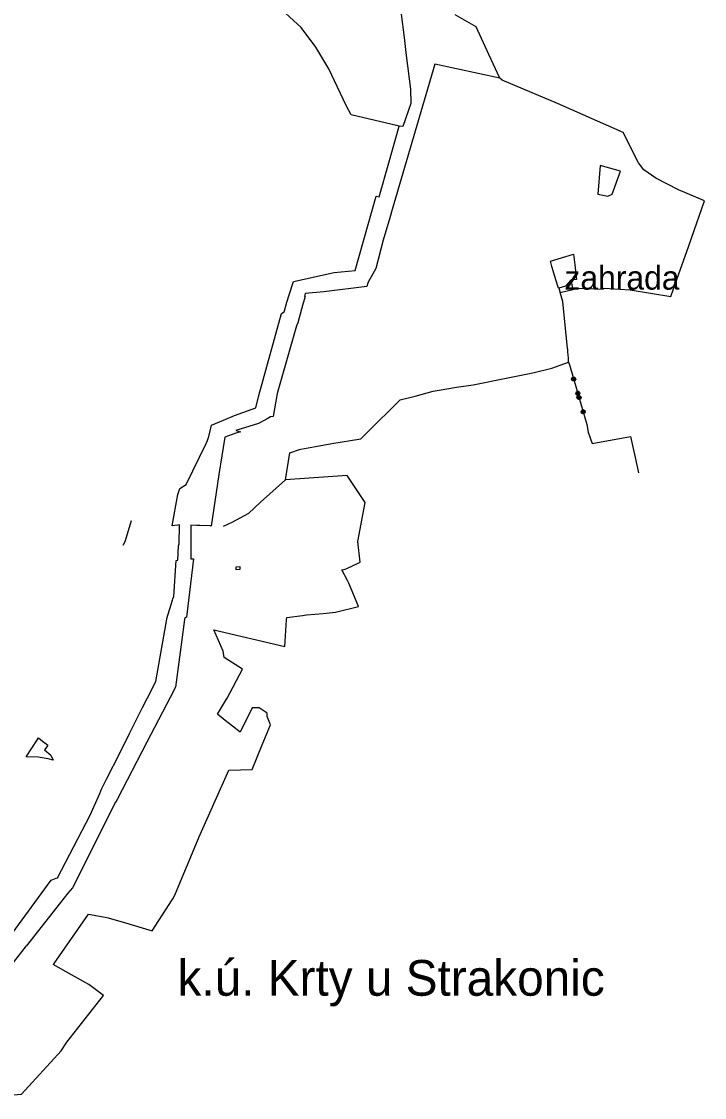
# Model space of a CAD drawing. Extents: x -800505 to -795586, y -1125317 to -1120396.
# Drawn here: x -796765 to -795617, y -1124292 to -1122485 of the extents above; entities that cross this region are included whole.
import ezdxf

# ---------------------------------------------------------------- set-up
doc = ezdxf.new("R2010")
doc.units = 0
for name, color, linetype in [('HRA_KU', 7, 'Continuous'), ('KU_OST', 7, 'Continuous'), ('LES_ZV', 7, 'Continuous'), ('Level 255', 7, 'Continuous'), ('OVNE_PRE', 7, 'Continuous'), ('OVNE_SET', 7, 'Continuous'), ('OVNI_SET', 7, 'Continuous'), ('TRV_POP', 7, 'Continuous'), ('TRV_ZV', 7, 'Continuous')]:
    doc.layers.add(name, color=color, linetype=linetype)

msp = doc.modelspace()

# ---------------------------------------------------------------- linework, layer by layer
at = {"layer": 'HRA_KU'}
for points in [[(-795845.8, -1123056.9), (-795843.6, -1123063.3), (-795814.8, -1123161.6), (-795812.6, -1123174.6), (-795806.1, -1123193.8), (-795741.5, -1123182.1), (-795734, -1123217), (-795728.4, -1123242.7)], [(-795833.7, -1123085.8), (-795835, -1123088.1), (-795837.6, -1123088.9), (-795839.9, -1123087.6), (-795840.7, -1123085), (-795839.4, -1123082.6), (-795836.8, -1123081.9), (-795834.5, -1123083.2), (-795833.7, -1123085.8), (-795834.1, -1123085.8), (-795834.8, -1123083.5), (-795835.8, -1123082.9), (-795834.7, -1123086.8), (-795835.2, -1123087.8), (-795836.8, -1123082.4), (-795837.5, -1123082.6), (-795836, -1123088), (-795836.7, -1123088.2), (-795838.3, -1123082.8), (-795839.1, -1123083.1), (-795837.5, -1123088.4), (-795838.5, -1123087.9), (-795839.6, -1123084), (-795840.2, -1123085), (-795839.5, -1123087.3)], [(-795826.7, -1123109.7), (-795828, -1123112.1), (-795830.6, -1123112.9), (-795832.9, -1123111.6), (-795833.7, -1123109), (-795832.4, -1123106.6), (-795829.8, -1123105.9), (-795827.4, -1123107.2), (-795826.7, -1123109.7), (-795827.1, -1123109.6), (-795827.8, -1123107.3), (-795828.8, -1123106.7), (-795827.7, -1123110.6), (-795828.2, -1123111.6), (-795829.8, -1123106.2), (-795830.6, -1123106.4), (-795829, -1123111.8), (-795829.8, -1123112), (-795831.3, -1123106.6), (-795832.1, -1123106.9), (-795830.5, -1123112.2), (-795831.5, -1123111.7), (-795832.6, -1123107.8), (-795833.2, -1123108.8), (-795832.5, -1123111.1)], [(-795824.6, -1123116.8), (-795825.9, -1123119.2), (-795828.5, -1123119.9), (-795830.8, -1123118.6), (-795831.6, -1123116), (-795830.3, -1123113.7), (-795827.7, -1123112.9), (-795825.4, -1123114.2), (-795824.6, -1123116.8), (-795825, -1123116.8), (-795825.7, -1123114.5), (-795826.7, -1123114), (-795825.6, -1123117.8), (-795826.1, -1123118.8), (-795827.7, -1123113.4), (-795828.4, -1123113.7), (-795826.9, -1123119), (-795827.6, -1123119.3), (-795829.2, -1123113.9), (-795830, -1123114.1), (-795828.4, -1123119.5), (-795829.4, -1123118.9), (-795830.5, -1123115.1), (-795831.1, -1123116.1), (-795830.4, -1123118.4)], [(-795817.6, -1123140.8), (-795818.9, -1123143.2), (-795821.5, -1123143.9), (-795823.8, -1123142.6), (-795824.6, -1123140), (-795823.3, -1123137.7), (-795820.7, -1123136.9), (-795818.3, -1123138.2), (-795817.6, -1123140.8), (-795818.1, -1123140.6), (-795818.7, -1123138.3), (-795819.7, -1123137.8), (-795818.6, -1123141.6), (-795819.1, -1123142.6), (-795820.7, -1123137.2), (-795821.5, -1123137.5), (-795819.9, -1123142.8), (-795820.7, -1123143.1), (-795822.3, -1123137.7), (-795823, -1123137.9), (-795821.4, -1123143.3), (-795822.4, -1123142.7), (-795823.6, -1123138.9), (-795824.1, -1123139.9), (-795823.4, -1123142.2)], [(-796321.4, -1123254.9), (-796363.2, -1123292.4), (-796383.6, -1123311), (-796411.3, -1123326.4), (-796426.1, -1123333.3)], [(-796580.8, -1123323.7), (-796591.5, -1123358.9), (-796594.9, -1123364.7)]]:
    msp.add_lwpolyline(points, dxfattribs=at)
at = {"layer": 'LES_ZV'}
for points in [[(-795961.3, -1122580.1), (-796070.3, -1122556.7), (-796142.1, -1122800.6), (-796146.2, -1122814.4), (-796157.1, -1122852.1), (-796169.6, -1122899.7), (-796182.7, -1122922.8), (-796183.2, -1122924.4), (-796184.6, -1122929.9), (-796256.9, -1122939), (-796288.3, -1122941.8), (-796289.7, -1122946.6), (-796288.5, -1122946.6), (-796292.7, -1122961.8), (-796294.3, -1122967.8), (-796300.7, -1122991.2), (-796303.1, -1122995.9), (-796335.5, -1123109.6), (-796342.3, -1123148.4), (-796346.6, -1123148.8), (-796352.3, -1123152), (-796366.7, -1123159.9), (-796405.1, -1123171.9), (-796397.1, -1123173.8), (-796404.8, -1123176.5), (-796423.6, -1123182.9), (-796433.7, -1123245.8)], [(-796511.9, -1123331.8), (-796502.4, -1123279.1), (-796498.9, -1123269.2), (-796488.5, -1123262.3), (-796454.9, -1123193.5), (-796452.7, -1123188.7), (-796450.3, -1123181.9), (-796446, -1123162.9), (-796425.4, -1123154.2), (-796407.1, -1123146.6), (-796371.3, -1123133.9), (-796366.4, -1123113.2), (-796328.3, -1122975.3), (-796323.6, -1122972.4), (-796323.2, -1122970.8), (-796318.9, -1122956.4), (-796314.7, -1122942), (-796307.8, -1122921.5), (-796239.5, -1122906.4), (-796204.2, -1122903.1), (-796169.1, -1122778.1), (-796163.8, -1122779.3), (-796147.7, -1122722), (-796130.5, -1122660.8)], [(-795792.8, -1122726.5), (-795796.3, -1122774.8), (-795779.7, -1122778.2), (-795772.5, -1122774.7), (-795758.6, -1122736.2), (-795792.8, -1122726.5)], [(-796433.7, -1123245.8), (-796446.1, -1123332.3), (-796447.7, -1123332.2), (-796465.3, -1123331.4), (-796470.2, -1123331.2), (-796480.5, -1123330.9), (-796480.4, -1123359.7), (-796480.4, -1123361.4), (-796480.4, -1123365.4), (-796480.3, -1123368.7), (-796480.3, -1123387.6), (-796478.3, -1123387.4), (-796476.1, -1123387.6)], [(-796505.4, -1123390.4), (-796502.5, -1123389.7), (-796501, -1123365.7), (-796500.1, -1123362.2), (-796499.4, -1123330.5), (-796502.6, -1123331.1), (-796511.9, -1123331.8)], [(-796846.6, -1124106.4), (-796715.4, -1123926.9), (-796707, -1123923.9), (-796704.4, -1123923), (-796649.4, -1123817.7), (-796633.2, -1123781.8), (-796631.9, -1123777), (-796630.5, -1123774.3), (-796622.1, -1123757.6), (-796599.5, -1123712.6), (-796583.4, -1123680.6), (-796568.9, -1123651.7), (-796561.7, -1123637.3), (-796553.9, -1123621.8), (-796539.5, -1123593.3), (-796521, -1123488.7), (-796520.8, -1123487.7), (-796511.3, -1123456.9), (-796510.6, -1123454.8), (-796508.9, -1123450.9), (-796505.4, -1123390.4)], [(-796476.1, -1123387.6), (-796487.9, -1123485.1), (-796491.1, -1123487.6), (-796491.3, -1123489.1), (-796496.4, -1123527.4), (-796506.5, -1123602.9), (-796506.6, -1123603.4), (-796508.7, -1123607.4), (-796554.3, -1123695.4), (-796604.1, -1123791.4), (-796606.8, -1123795.9), (-796679.6, -1123939.7), (-796686.9, -1123948.9), (-796699.5, -1123964.8), (-796757.4, -1124037.8), (-796758.6, -1124039.3), (-796759, -1124039.8), (-796821.2, -1124118.1)]]:
    msp.add_lwpolyline(points, dxfattribs=at)
at = {"layer": 'Level 255'}
for points in [[(-796398.2, -1123400.5), (-796398.1, -1123405.5), (-796404.1, -1123405.6), (-796404.2, -1123400.7), (-796398.2, -1123400.5)], [(-796736.5, -1123688.1), (-796729.7, -1123693.5), (-796725.7, -1123696.7), (-796720.8, -1123700.5), (-796722.4, -1123702.9), (-796726.2, -1123708.4), (-796715.8, -1123717), (-796711.7, -1123725.3), (-796720.3, -1123723.3), (-796737.3, -1123720.7), (-796757, -1123720.1), (-796738.1, -1123690.6), (-796736.5, -1123688.1)]]:
    msp.add_lwpolyline(points, dxfattribs=at)
at = {"layer": 'OVNE_PRE'}
msp.add_lwpolyline([(-796831, -1124292.1), (-796765, -1124286.6), (-796698.1, -1124213.5), (-796689, -1124199.4), (-796627, -1124121), (-796651.7, -1124102.3), (-796680.8, -1124086.1), (-796711.7, -1124068.9), (-796710.2, -1124066.8), (-796652.6, -1123984.2), (-796624.5, -1123989.3), (-796619.5, -1123990.2), (-796590.1, -1123999), (-796545.4, -1124012.3), (-796511.7, -1123960.1), (-796510.8, -1123958.5), (-796507.8, -1123953.4), (-796506.1, -1123949.7), (-796469.2, -1123861), (-796467.4, -1123857), (-796466.8, -1123855.7), (-796416.6, -1123742.5), (-796377.3, -1123741), (-796360.6, -1123700), (-796346.8, -1123666.3), (-796352.2, -1123652.3), (-796352.1, -1123646.6), (-796365.5, -1123637.8), (-796377.6, -1123637.6), (-796397.7, -1123678.7), (-796410.3, -1123668.6), (-796422.6, -1123658.8), (-796435.5, -1123648.5), (-796420.3, -1123623.2), (-796419.3, -1123621.3), (-796393.8, -1123572.6), (-796412.1, -1123561), (-796424.6, -1123553.1), (-796426.1, -1123542.3), (-796441.6, -1123506.9), (-796322.7, -1123534.7), (-796320.7, -1123507.6), (-796319.6, -1123489.8), (-796319.2, -1123486.1), (-796292.8, -1123482.4), (-796286, -1123481.5), (-796258.3, -1123479), (-796237.4, -1123477.2), (-796198.8, -1123467.3), (-796214.8, -1123428.3), (-796217.1, -1123423.8), (-796226.6, -1123405.7), (-796224, -1123405.4), (-796221.3, -1123404.9), (-796218.6, -1123403.5), (-796197.1, -1123393.3), (-796196.2, -1123392.9), (-796200, -1123358.2), (-796187.3, -1123292.8), (-796217.6, -1123247.6), (-796321.4, -1123254.9), (-796314, -1123209.4), (-796297.7, -1123203.6), (-796295.7, -1123202.9), (-796271.2, -1123198.5), (-796243.4, -1123193.4), (-796195, -1123185.9), (-796190.2, -1123181.2), (-796187.6, -1123178.6), (-796185.5, -1123176.5), (-796128.9, -1123120.4), (-796103.6, -1123113.9), (-796073.5, -1123105.8), (-796063.1, -1123104.2), (-796034.2, -1123099.2), (-796006, -1123094.9), (-795950.4, -1123083.7), (-795905.9, -1123074.8), (-795873.8, -1123067.2), (-795845.8, -1123056.9)], dxfattribs=at)
at = {"layer": 'OVNE_SET'}
for points in [[(-796127.1, -1122472.5), (-796122.1, -1122511.7), (-796118.8, -1122541.7), (-796111.4, -1122598.3), (-796110.6, -1122622.5), (-796124.1, -1122661.3), (-796130.5, -1122660.8), (-796132.8, -1122660.3), (-796211.1, -1122641.6), (-796219.5, -1122626.2), (-796234.1, -1122595.2), (-796248.6, -1122564.3), (-796270.4, -1122527.8), (-796295, -1122494.7), (-796327.8, -1122465.1)], [(-795845.8, -1123056.9), (-795846.1, -1123049.8), (-795846.5, -1123045.2), (-795846.7, -1123039.8), (-795847.1, -1123035.8), (-795847.3, -1123034), (-795855.4, -1122954.9), (-795859.9, -1122940), (-795838.4, -1122934.8), (-795829.7, -1122932.8), (-795787, -1122934.2), (-795787.4, -1122932.6), (-795777.2, -1122933.2), (-795742.2, -1122935.4), (-795673.9, -1122946.8), (-795669.4, -1122934.1), (-795643.7, -1122861.9), (-795617.3, -1122786.3), (-795661.2, -1122767.5), (-795699, -1122748), (-795719.4, -1122734), (-795728.3, -1122722.4), (-795753.7, -1122671.2), (-795864.2, -1122622.4), (-795957.3, -1122583.2), (-795961.3, -1122580.1), (-795979.6, -1122540.3), (-796000.8, -1122494), (-796036.5, -1122473.4)]]:
    msp.add_lwpolyline(points, dxfattribs=at)
at = {"layer": 'OVNI_SET'}
msp.add_lwpolyline([(-795851.1, -1122929.3), (-795862.1, -1122932.8), (-795862.5, -1122932.9), (-795864.2, -1122927.6), (-795864.5, -1122927.8), (-795865.7, -1122924.1), (-795865.3, -1122924), (-795866.5, -1122920.2), (-795873.7, -1122896.2), (-795876.1, -1122887.2), (-795837.2, -1122875.7), (-795835, -1122893.5), (-795832.9, -1122914.2), (-795832.4, -1122918.4), (-795841.9, -1122919.5), (-795851.1, -1122929.3)], dxfattribs=at)
at = {"layer": 'TRV_ZV'}
msp.add_line((-795862.1, -1122932.8), (-795859.9, -1122940), dxfattribs=at)
msp.add_lwpolyline([(-795841.9, -1122919.5), (-795840.1, -1122927.2), (-795838.4, -1122934.8)], dxfattribs=at)

# ---------------------------------------------------------------- texts
at = {"layer": 'KU_OST'}
msp.add_text('k.ú. Krty u Strakonic', height=60, dxfattribs=at).set_placement((-796502.9, -1124121.2))
at = {"layer": 'TRV_POP'}
msp.add_text('zahrada', height=40, dxfattribs=at).set_placement((-795852.6, -1122935.2))

doc.saveas('drawing.dxf')
